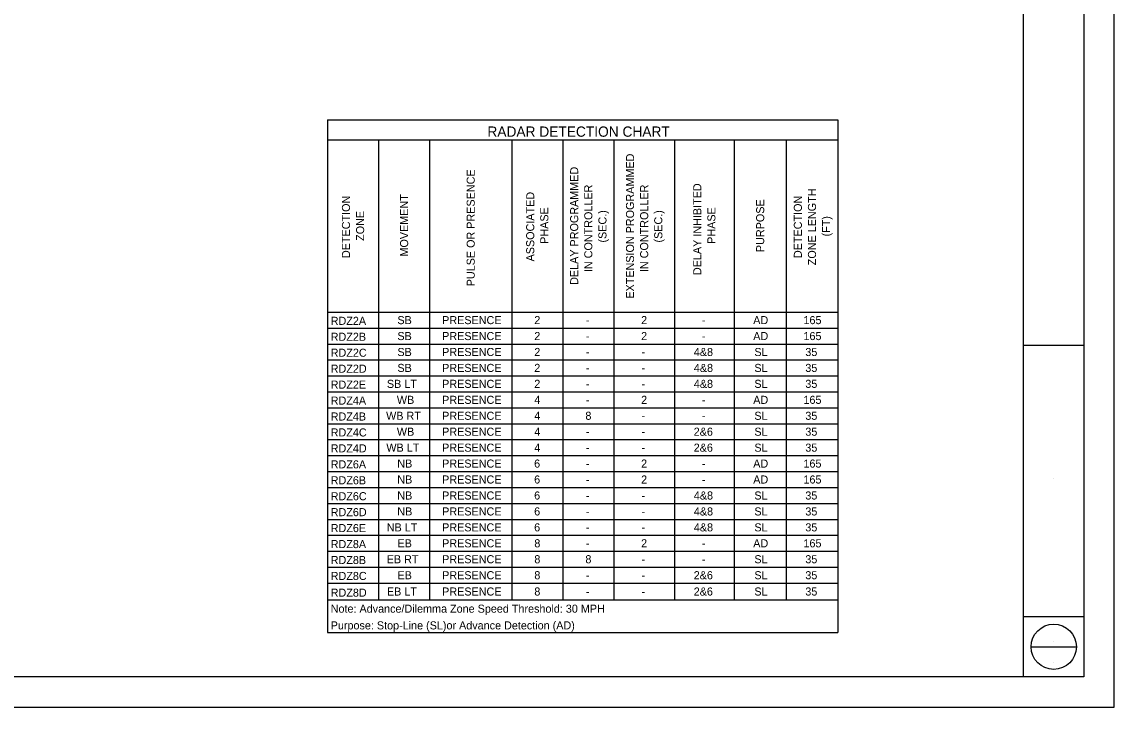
# Model space of a CAD drawing. Extents: x 22.8 to 118.4, y -49.9 to 44.8.
# Drawn here: x 57.13 to 75.22, y 18.6 to 29.96 of the extents above; entities that cross this region are included whole.
import ezdxf

# ---------------------------------------------------------------- set-up
doc = ezdxf.new("R2010")
doc.units = 0
for name, color, linetype in [('SH_Border', 7, 'Continuous'), ('SH_Cut_Line', 7, 'Continuous'), ('SH_Data', 7, 'Continuous'), ('SH_Text', 7, 'Continuous')]:
    doc.layers.add(name, color=color, linetype=linetype)

msp = doc.modelspace()

# ---------------------------------------------------------------- linework, layer by layer
at = {"layer": 'SH_Border'}
for p, q in [((73.72, 19.104), (73.72, 40.104)), ((62.191, 28.333), (70.645, 28.333)), ((62.191, 28.333), (62.191, 19.839)), ((70.645, 28.333), (70.645, 19.839)), ((62.191, 28.003), (70.645, 28.003)), ((63.036, 28.003), (63.036, 20.381)), ((63.881, 28.003), (63.881, 20.381)), ((65.242, 28.003), (65.242, 20.381)), ((66.087, 28.003), (66.087, 20.381)), ((66.933, 28.003), (66.933, 20.381)), ((67.937, 28.003), (67.937, 20.381)), ((68.927, 28.003), (68.927, 20.381)), ((69.786, 28.003), (69.786, 20.381)), ((62.191, 25.149), (70.645, 25.149)), ((62.191, 24.885), (70.645, 24.885)), ((62.191, 24.621), (70.645, 24.621)), ((73.72, 24.604), (74.72, 24.604)), ((62.191, 24.357), (70.645, 24.357)), ((62.191, 24.093), (70.645, 24.093)), ((62.191, 23.828), (70.645, 23.828)), ((62.191, 23.564), (70.645, 23.564)), ((62.191, 23.3), (70.645, 23.3)), ((62.191, 23.036), (70.645, 23.036)), ((62.191, 22.772), (70.645, 22.772)), ((62.191, 22.507), (70.645, 22.507)), ((62.191, 22.243), (70.645, 22.243)), ((62.191, 21.979), (70.645, 21.979)), ((62.191, 21.715), (70.645, 21.715)), ((62.191, 21.451), (70.645, 21.451)), ((62.191, 21.187), (70.645, 21.187)), ((62.191, 20.922), (70.645, 20.922)), ((62.191, 20.658), (70.645, 20.658)), ((62.191, 20.381), (70.645, 20.381)), ((73.72, 20.104), (74.72, 20.104)), ((62.191, 19.839), (70.645, 19.839))]:
    msp.add_line(p, q, dxfattribs=at)
msp.add_lwpolyline([(43.22, 40.104), (74.72, 40.104), (74.72, 19.104), (43.22, 19.104)], close=True, dxfattribs=at)
at = {"layer": 'SH_Cut_Line'}
msp.add_lwpolyline([(41.22, 18.604), (75.22, 18.604), (75.22, 40.604), (41.22, 40.604)], close=True, dxfattribs=at)
at = {"layer": 'SH_Data'}
for p, q in [((74.22, 22.395), (74.22, 22.395)), ((73.845, 19.604), (74.595, 19.604)), ((74.22, 19.689), (74.22, 19.689)), ((74.22, 19.349), (74.22, 19.349))]:
    msp.add_line(p, q, dxfattribs=at)
msp.add_circle((74.22, 19.604), 0.375, dxfattribs=at)

# ---------------------------------------------------------------- texts
at = {"layer": 'SH_Text'}
for s, height, p in [('RADAR DETECTION CHART', 0.17014, (64.839, 28.055)), ('RDZ2A', 0.1337, (62.243, 24.938)), ('SB', 0.1337, (63.348, 24.95)), ('PRESENCE', 0.1337, (64.089, 24.95)), ('2', 0.134, (65.615, 24.95)), ('-', 0.134, (66.469, 24.95)), ('2', 0.134, (67.385, 24.95)), ('-', 0.134, (68.39, 24.95)), ('AD', 0.1337, (69.242, 24.95)), ('165', 0.1337, (70.074, 24.95)), ('RDZ2B', 0.1337, (62.243, 24.674)), ('SB', 0.1337, (63.348, 24.686)), ('PRESENCE', 0.1337, (64.089, 24.686)), ('2', 0.134, (65.615, 24.686)), ('2', 0.134, (67.385, 24.686)), ('AD', 0.1337, (69.242, 24.686)), ('165', 0.1337, (70.074, 24.686)), ('-', 0.134, (66.469, 24.686)), ('-', 0.134, (68.39, 24.686)), ('RDZ2C', 0.1337, (62.243, 24.41)), ('SB', 0.1337, (63.348, 24.422)), ('PRESENCE', 0.1337, (64.089, 24.422)), ('2', 0.134, (65.615, 24.422)), ('-', 0.134, (66.469, 24.422)), ('-', 0.134, (67.393, 24.422)), ('4&8', 0.1337, (68.258, 24.422)), ('SL', 0.1337, (69.261, 24.422)), ('35', 0.1337, (70.105, 24.422)), ('RDZ2D', 0.1337, (62.243, 24.145)), ('SB', 0.1337, (63.348, 24.158)), ('PRESENCE', 0.1337, (64.089, 24.158)), ('2', 0.134, (65.615, 24.158)), ('4&8', 0.1337, (68.258, 24.158)), ('SL', 0.1337, (69.261, 24.158)), ('35', 0.1337, (70.105, 24.158)), ('-', 0.134, (66.469, 24.158)), ('-', 0.134, (67.393, 24.158)), ('RDZ2E', 0.1337, (62.243, 23.881)), ('SB LT', 0.1337, (63.174, 23.894)), ('PRESENCE', 0.1337, (64.089, 23.894)), ('2', 0.134, (65.615, 23.894)), ('-', 0.134, (66.469, 23.894)), ('-', 0.134, (67.393, 23.894)), ('4&8', 0.1337, (68.258, 23.894)), ('SL', 0.1337, (69.261, 23.894)), ('35', 0.1337, (70.105, 23.894)), ('RDZ4A', 0.1337, (62.243, 23.617)), ('WB', 0.1337, (63.339, 23.629)), ('PRESENCE', 0.1337, (64.089, 23.629)), ('4', 0.134, (65.615, 23.629)), ('2', 0.134, (67.385, 23.629)), ('AD', 0.1337, (69.242, 23.629)), ('165', 0.1337, (70.074, 23.629)), ('-', 0.134, (66.469, 23.629)), ('-', 0.134, (68.39, 23.629)), ('RDZ4B', 0.1337, (62.243, 23.353)), ('WB RT', 0.1337, (63.161, 23.365)), ('PRESENCE', 0.1337, (64.089, 23.365)), ('4', 0.134, (65.615, 23.365)), ('8', 0.134, (66.462, 23.365)), ('-', 0.134, (67.393, 23.365)), ('-', 0.134, (68.39, 23.365)), ('SL', 0.1337, (69.261, 23.365)), ('35', 0.1337, (70.105, 23.365)), ('RDZ4C', 0.1337, (62.243, 23.089)), ('WB', 0.1337, (63.339, 23.101)), ('PRESENCE', 0.1337, (64.089, 23.101)), ('4', 0.134, (65.615, 23.101)), ('-', 0.134, (66.469, 23.101)), ('-', 0.134, (67.393, 23.101)), ('2&6', 0.1337, (68.256, 23.101)), ('SL', 0.1337, (69.261, 23.101)), ('35', 0.1337, (70.105, 23.101)), ('RDZ4D', 0.1337, (62.243, 22.825)), ('WB LT', 0.1337, (63.165, 22.837)), ('PRESENCE', 0.1337, (64.089, 22.837)), ('4', 0.134, (65.615, 22.837)), ('-', 0.134, (66.469, 22.837)), ('-', 0.134, (67.393, 22.837)), ('2&6', 0.1337, (68.256, 22.837)), ('SL', 0.1337, (69.261, 22.837)), ('35', 0.1337, (70.105, 22.837)), ('RDZ6A', 0.1337, (62.243, 22.56)), ('NB', 0.1337, (63.346, 22.573)), ('PRESENCE', 0.1337, (64.089, 22.573)), ('6', 0.134, (65.613, 22.573)), ('-', 0.134, (66.469, 22.573)), ('2', 0.134, (67.385, 22.573)), ('-', 0.134, (68.39, 22.573)), ('AD', 0.1337, (69.242, 22.573)), ('165', 0.1337, (70.074, 22.573)), ('NB', 0.1337, (63.346, 22.309)), ('PRESENCE', 0.1337, (64.089, 22.309)), ('6', 0.134, (65.613, 22.309)), ('2', 0.134, (67.385, 22.309)), ('AD', 0.1337, (69.242, 22.309)), ('165', 0.1337, (70.074, 22.309)), ('RDZ6B', 0.1337, (62.243, 22.296)), ('-', 0.134, (66.469, 22.309)), ('-', 0.134, (68.39, 22.309)), ('RDZ6C', 0.1337, (62.243, 22.032)), ('NB', 0.1337, (63.346, 22.044)), ('PRESENCE', 0.1337, (64.089, 22.044)), ('6', 0.134, (65.613, 22.044)), ('-', 0.134, (66.469, 22.044)), ('-', 0.134, (67.393, 22.044)), ('4&8', 0.1337, (68.258, 22.044)), ('SL', 0.1337, (69.261, 22.044)), ('35', 0.1337, (70.105, 22.044)), ('RDZ6D', 0.1337, (62.243, 21.768)), ('NB', 0.1337, (63.346, 21.78)), ('PRESENCE', 0.1337, (64.089, 21.78)), ('6', 0.134, (65.613, 21.78)), ('4&8', 0.1337, (68.258, 21.78)), ('SL', 0.1337, (69.261, 21.78)), ('35', 0.1337, (70.105, 21.78)), ('-', 0.134, (66.469, 21.78)), ('-', 0.134, (67.393, 21.78)), ('RDZ6E', 0.1337, (62.243, 21.504)), ('NB LT', 0.1337, (63.172, 21.516)), ('PRESENCE', 0.1337, (64.089, 21.516)), ('6', 0.134, (65.613, 21.516)), ('-', 0.134, (66.469, 21.516)), ('-', 0.134, (67.393, 21.516)), ('4&8', 0.1337, (68.258, 21.516)), ('SL', 0.1337, (69.261, 21.516)), ('35', 0.1337, (70.105, 21.516)), ('RDZ8A', 0.1337, (62.243, 21.239)), ('EB', 0.1337, (63.349, 21.252)), ('PRESENCE', 0.1337, (64.089, 21.252)), ('8', 0.134, (65.616, 21.252)), ('2', 0.134, (67.385, 21.252)), ('AD', 0.1337, (69.242, 21.252)), ('165', 0.1337, (70.074, 21.252)), ('-', 0.134, (66.469, 21.252)), ('-', 0.134, (68.39, 21.252)), ('RDZ8B', 0.1337, (62.243, 20.975)), ('EB RT', 0.1337, (63.171, 20.988)), ('PRESENCE', 0.1337, (64.089, 20.988)), ('8', 0.134, (65.616, 20.988)), ('8', 0.134, (66.462, 20.988)), ('-', 0.134, (67.393, 20.988)), ('-', 0.134, (68.39, 20.988)), ('SL', 0.1337, (69.261, 20.988)), ('35', 0.1337, (70.105, 20.988)), ('RDZ8C', 0.1337, (62.243, 20.711)), ('EB', 0.1337, (63.349, 20.723)), ('PRESENCE', 0.1337, (64.089, 20.723)), ('8', 0.134, (65.616, 20.723)), ('2&6', 0.1337, (68.256, 20.723)), ('SL', 0.1337, (69.261, 20.723)), ('35', 0.1337, (70.105, 20.723)), ('-', 0.134, (66.469, 20.723)), ('-', 0.134, (67.393, 20.723)), ('RDZ8D', 0.1337, (62.243, 20.434)), ('EB LT', 0.1337, (63.175, 20.453)), ('PRESENCE', 0.1337, (64.089, 20.453)), ('8', 0.134, (65.616, 20.453)), ('-', 0.134, (66.469, 20.453)), ('-', 0.134, (67.393, 20.453)), ('2&6', 0.1337, (68.256, 20.453)), ('SL', 0.1337, (69.261, 20.453)), ('35', 0.1337, (70.105, 20.453)), ('Note: Advance/Dilemma Zone Speed Threshold: 30 MPH', 0.13368, (62.243, 20.169)), ('Purpose: Stop-Line (SL)or Advance Detection (AD)', 0.13368, (62.243, 19.892))]:
    msp.add_text(s, height=height, dxfattribs=at).set_placement(p)
for s, height, p in [('EXTENSION PROGRAMMED', 0.13368, (67.268, 25.372)), ('PULSE OR PRESENCE', 0.13368, (64.629, 25.577)), ('DELAY PROGRAMMED', 0.13368, (66.343, 25.601)), ('IN CONTROLLER', 0.13368, (66.577, 25.812)), ('IN CONTROLLER', 0.13368, (67.502, 25.812)), ('DELAY INHIBITED', 0.13368, (68.382, 25.763)), ('ZONE LENGTH', 0.13368, (70.282, 25.926)), ('DETECTION', 0.1337, (62.563, 26.045)), ('MOVEMENT', 0.1337, (63.526, 26.07)), ('ASSOCIATED', 0.1337, (65.615, 25.989)), ('PURPOSE', 0.1337, (69.424, 26.144)), ('DETECTION', 0.1337, (70.048, 26.045)), ('ZONE', 0.1337, (62.797, 26.33)), ('PHASE', 0.1337, (65.848, 26.281)), ('(SEC.)', 0.1337, (66.811, 26.302)), ('(SEC.)', 0.1337, (67.736, 26.302)), ('PHASE', 0.1337, (68.616, 26.281)), ('(FT)', 0.1337, (70.516, 26.403))]:
    msp.add_text(s, height=height, rotation=90, dxfattribs=at).set_placement(p)

doc.saveas('drawing.dxf')
